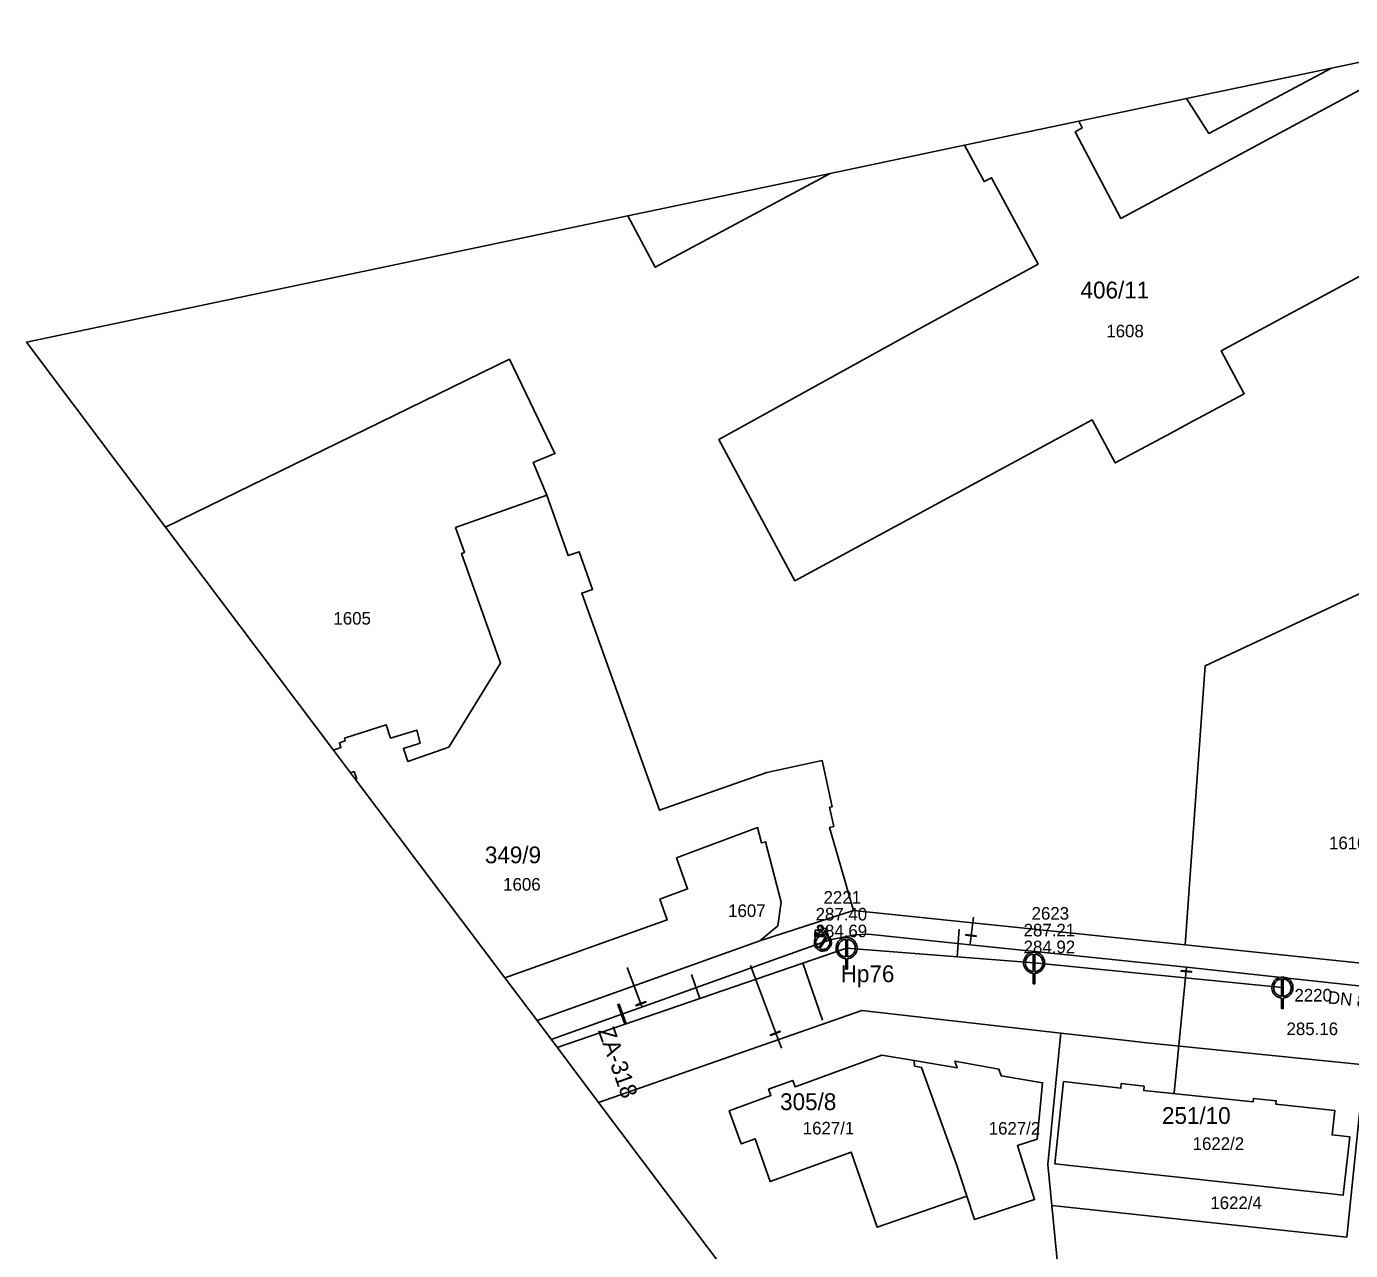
# Model space of a CAD drawing. Extents: x -570698 to -570232, y -1086952 to -1086596.
# Drawn here: x -570698.4 to -570540.7, y -1086773.3 to -1086627.6 of the extents above; entities that cross this region are included whole.
import ezdxf

# ---------------------------------------------------------------- set-up
doc = ezdxf.new("R2010")
doc.units = 0
for name, color, linetype in [('Adresní místo-text', 7, 'Continuous'), ('Armatura - popis', 7, 'Continuous'), ('Armatura vodovodní', 7, 'Continuous'), ('Default', 7, 'Continuous'), ('Hydrant', 7, 'Continuous'), ('Kanalizační přípojka', 7, 'Continuous'), ('Kanalizační stoka', 7, 'Continuous'), ('Kanalizační šachta', 7, 'Continuous'), ('Označení hydrantu', 7, 'Continuous'), ('Parcela-polygon', 7, 'Continuous'), ('Parcela-text', 7, 'Continuous'), ('Popis šachty', 7, 'Continuous'), ('Vodovodní přípojka', 7, 'Continuous'), ('Vodovodní řad', 7, 'Continuous'), ('Řad vodovodní popis', 7, 'Continuous')]:
    doc.layers.add(name, color=color, linetype=linetype)

msp = doc.modelspace()

# ---------------------------------------------------------------- linework, layer by layer
at = {"layer": 'Armatura vodovodní'}
for points in [[(-570586.5, -1086735.7), (-570585.26, -1086735.86), (-570585.27, -1086735.93), (-570586.51, -1086735.78), (-570586.5, -1086735.7)], [(-570560.83, -1086740), (-570559.59, -1086740.12), (-570559.6, -1086740.2), (-570560.84, -1086740.08), (-570560.83, -1086740)], [(-570627.8, -1086743.99), (-570626.96, -1086746.35), (-570627.11, -1086746.4), (-570627.95, -1086744.04), (-570627.8, -1086743.99)], [(-570625.79, -1086744.13), (-570624.62, -1086743.69), (-570624.6, -1086743.76), (-570625.76, -1086744.21), (-570625.79, -1086744.13)], [(-570608.56, -1086747.28), (-570609.73, -1086747.72), (-570609.76, -1086747.65), (-570608.59, -1086747.21), (-570608.56, -1086747.28)]]:
    msp.add_lwpolyline(points, dxfattribs=at)
at = {"layer": 'Default'}
for points, degree in [([(-570604.47, -1086735.76), (-570604.47, -1086735.48), (-570604.42, -1086735.2)], 2), ([(-570604.11, -1086735.33), (-570604.1, -1086735.01), (-570604.01, -1086734.73)], 2), ([(-570603.56, -1086735.5), (-570603.66, -1086735.2), (-570603.86, -1086734.96), (-570603.95, -1086735.25), (-570603.93, -1086735.57)], 3), ([(-570603.81, -1086734.69), (-570603.61, -1086734.91), (-570603.48, -1086735.21)], 2), ([(-570603.25, -1086734.96), (-570603.09, -1086735.21), (-570602.99, -1086735.46)], 2), ([(-570602.85, -1086735.92), (-570602.61, -1086736.14), (-570602.54, -1086736.48), (-570602.46, -1086736.88), (-570602.69, -1086737.23), (-570602.92, -1086737.57), (-570603.33, -1086737.65), (-570603.73, -1086737.73), (-570604.07, -1086737.5), (-570604.42, -1086737.27), (-570604.5, -1086736.87), (-570604.57, -1086736.53), (-570604.42, -1086736.23)], 3), ([(-570604.45, -1086736.27), (-570604.43, -1086736.25), (-570604.42, -1086736.23), (-570604.45, -1086736.07), (-570604.46, -1086735.96)], 3), ([(-570603.15, -1086735.94), (-570603.39, -1086735.81), (-570603.68, -1086735.87), (-570604.01, -1086735.94), (-570604.2, -1086736.22), (-570604.38, -1086736.5), (-570604.32, -1086736.83), (-570604.26, -1086737.11), (-570604.05, -1086737.29)], 3), ([(-570604.28, -1086735.43), (-570604.29, -1086735.71), (-570604.26, -1086735.99)], 2), ([(-570604.26, -1086735.99), (-570604.08, -1086735.79), (-570603.8, -1086735.71)], 2), ([(-570603.89, -1086737.39), (-570603.65, -1086737.52), (-570603.36, -1086737.46), (-570603.03, -1086737.4), (-570602.85, -1086737.12), (-570602.66, -1086736.84), (-570602.72, -1086736.51), (-570602.78, -1086736.23), (-570602.99, -1086736.05)], 3), ([(-570603.62, -1086735.67), (-570603.34, -1086735.64), (-570603.1, -1086735.76), (-570603.17, -1086735.49), (-570603.3, -1086735.23)], 3), ([(-570602.89, -1086735.77), (-570602.88, -1086735.8), (-570602.85, -1086735.92)], 2), ([(-570600.79, -1086738.58), (-570601.05, -1086738.56), (-570601.31, -1086738.41), (-570601.61, -1086738.25), (-570601.78, -1086737.95), (-570601.94, -1086737.65), (-570601.94, -1086737.33), (-570601.94, -1086737), (-570601.77, -1086736.7), (-570601.6, -1086736.4), (-570601.31, -1086736.24), (-570601.01, -1086736.08), (-570600.69, -1086736.08), (-570600.38, -1086736.08), (-570600.08, -1086736.24), (-570599.78, -1086736.4), (-570599.61, -1086736.7), (-570599.44, -1086737), (-570599.44, -1086737.33), (-570599.44, -1086737.65), (-570599.6, -1086737.95), (-570599.77, -1086738.25), (-570600.07, -1086738.41), (-570600.33, -1086738.56), (-570600.59, -1086738.58)], 3), ([(-570600.79, -1086736.29), (-570600.99, -1086736.31), (-570601.21, -1086736.42), (-570601.45, -1086736.56), (-570601.59, -1086736.81), (-570601.73, -1086737.06), (-570601.73, -1086737.33), (-570601.73, -1086737.6), (-570601.6, -1086737.85), (-570601.46, -1086738.09), (-570601.21, -1086738.23), (-570601, -1086738.35), (-570600.79, -1086738.37)], 3), ([(-570600.59, -1086738.37), (-570600.38, -1086738.35), (-570600.17, -1086738.23), (-570599.92, -1086738.09), (-570599.78, -1086737.85), (-570599.65, -1086737.6), (-570599.65, -1086737.33), (-570599.65, -1086737.06), (-570599.79, -1086736.81), (-570599.93, -1086736.56), (-570600.18, -1086736.42), (-570600.39, -1086736.31), (-570600.59, -1086736.29)], 3), ([(-570578.45, -1086740.33), (-570578.71, -1086740.31), (-570578.97, -1086740.16), (-570579.27, -1086740), (-570579.44, -1086739.7), (-570579.6, -1086739.4), (-570579.6, -1086739.08), (-570579.6, -1086738.75), (-570579.43, -1086738.45), (-570579.26, -1086738.15), (-570578.97, -1086737.99), (-570578.67, -1086737.83), (-570578.35, -1086737.83), (-570578.04, -1086737.83), (-570577.74, -1086737.99), (-570577.44, -1086738.15), (-570577.27, -1086738.45), (-570577.1, -1086738.75), (-570577.1, -1086739.08), (-570577.1, -1086739.4), (-570577.26, -1086739.7), (-570577.43, -1086740), (-570577.73, -1086740.16), (-570577.99, -1086740.31), (-570578.25, -1086740.33)], 3), ([(-570578.45, -1086738.04), (-570578.65, -1086738.06), (-570578.87, -1086738.17), (-570579.11, -1086738.31), (-570579.25, -1086738.56), (-570579.39, -1086738.81), (-570579.39, -1086739.08), (-570579.39, -1086739.35), (-570579.26, -1086739.6), (-570579.12, -1086739.84), (-570578.87, -1086739.98), (-570578.66, -1086740.1), (-570578.45, -1086740.12)], 3), ([(-570578.25, -1086740.12), (-570578.04, -1086740.1), (-570577.83, -1086739.98), (-570577.58, -1086739.84), (-570577.44, -1086739.6), (-570577.31, -1086739.35), (-570577.31, -1086739.08), (-570577.31, -1086738.81), (-570577.45, -1086738.56), (-570577.59, -1086738.31), (-570577.84, -1086738.17), (-570578.05, -1086738.06), (-570578.25, -1086738.04)], 3), ([(-570548.87, -1086743.29), (-570549.13, -1086743.27), (-570549.39, -1086743.12), (-570549.69, -1086742.96), (-570549.86, -1086742.66), (-570550.02, -1086742.36), (-570550.02, -1086742.04), (-570550.02, -1086741.71), (-570549.85, -1086741.41), (-570549.68, -1086741.11), (-570549.39, -1086740.95), (-570549.09, -1086740.79), (-570548.77, -1086740.79), (-570548.46, -1086740.79), (-570548.16, -1086740.95), (-570547.86, -1086741.11), (-570547.69, -1086741.41), (-570547.52, -1086741.71), (-570547.52, -1086742.04), (-570547.52, -1086742.36), (-570547.68, -1086742.66), (-570547.85, -1086742.96), (-570548.15, -1086743.12), (-570548.41, -1086743.27), (-570548.67, -1086743.29)], 3), ([(-570548.87, -1086741), (-570549.07, -1086741.02), (-570549.29, -1086741.13), (-570549.53, -1086741.27), (-570549.67, -1086741.52), (-570549.81, -1086741.77), (-570549.81, -1086742.04), (-570549.81, -1086742.31), (-570549.68, -1086742.56), (-570549.54, -1086742.8), (-570549.29, -1086742.94), (-570549.08, -1086743.06), (-570548.87, -1086743.08)], 3), ([(-570548.67, -1086743.08), (-570548.46, -1086743.06), (-570548.25, -1086742.94), (-570548, -1086742.8), (-570547.86, -1086742.56), (-570547.73, -1086742.31), (-570547.73, -1086742.04), (-570547.73, -1086741.77), (-570547.87, -1086741.52), (-570548.01, -1086741.27), (-570548.26, -1086741.13), (-570548.47, -1086741.02), (-570548.67, -1086741)], 3)]:
    msp.add_open_spline(points, degree=degree, dxfattribs=at)
at = {"layer": 'Hydrant'}
for points in [[(-570604.42, -1086735.2), (-570604.23, -1086735.16), (-570604.11, -1086735.33)], [(-570604.01, -1086734.73), (-570603.81, -1086734.69)], [(-570603.48, -1086735.21), (-570603.44, -1086735), (-570603.25, -1086734.96)], [(-570604.46, -1086735.96), (-570604.47, -1086735.76)], [(-570604.42, -1086736.23), (-570604.45, -1086736.27)], [(-570603.93, -1086735.57), (-570604.12, -1086735.61), (-570604.28, -1086735.43)], [(-570604.05, -1086737.29), (-570603.15, -1086735.94)], [(-570602.99, -1086736.05), (-570603.89, -1086737.39)], [(-570603.8, -1086735.71), (-570603.62, -1086735.67)], [(-570603.3, -1086735.23), (-570603.37, -1086735.46), (-570603.56, -1086735.5)], [(-570602.99, -1086735.46), (-570602.92, -1086735.66), (-570602.89, -1086735.77)]]:
    msp.add_lwpolyline(points, dxfattribs=at)
at = {"layer": 'Kanalizační přípojka'}
for points in [[(-570587.26, -1086735.07), (-570587.52, -1086738.36)], [(-570603.56, -1086745.93), (-570605.89, -1086739.11)], [(-570619.16, -1086740.49), (-570618.19, -1086743.33)]]:
    msp.add_lwpolyline(points, dxfattribs=at)
at = {"layer": 'Kanalizační stoka'}
for points in [[(-570600.69, -1086737.33), (-570619.34, -1086743.73), (-570635.16, -1086749.15)], [(-570578.35, -1086739.08), (-570600.69, -1086737.33)], [(-570548.77, -1086742.04), (-570578.35, -1086739.08)]]:
    msp.add_lwpolyline(points, dxfattribs=at)
at = {"layer": 'Kanalizační šachta'}
for points in [[(-570600.79, -1086738.37), (-570600.79, -1086736.29)], [(-570600.59, -1086736.29), (-570600.59, -1086738.37)], [(-570578.45, -1086740.12), (-570578.45, -1086738.04)], [(-570578.25, -1086738.04), (-570578.25, -1086740.12)], [(-570600.59, -1086738.58), (-570600.59, -1086739.83), (-570600.79, -1086739.83), (-570600.79, -1086738.58)], [(-570578.25, -1086740.33), (-570578.25, -1086741.58), (-570578.45, -1086741.58), (-570578.45, -1086740.33)], [(-570548.87, -1086743.08), (-570548.87, -1086741)], [(-570548.67, -1086741), (-570548.67, -1086743.08)], [(-570548.67, -1086743.29), (-570548.67, -1086744.54), (-570548.87, -1086744.54), (-570548.87, -1086743.29)]]:
    msp.add_lwpolyline(points, dxfattribs=at)
at = {"layer": 'Parcela-polygon'}
for p, q in [((-570519.33, -1086627.59), (-570542.91, -1086632.54)), ((-570542.91, -1086632.54), (-570560.18, -1086636.17)), ((-570560.18, -1086636.17), (-570573.04, -1086638.87)), ((-570573.04, -1086638.87), (-570586.66, -1086641.72)), ((-570586.66, -1086641.72), (-570602.65, -1086645.08)), ((-570602.65, -1086645.08), (-570626.76, -1086650.14)), ((-570681.81, -1086687.2), (-570661.8, -1086713.76)), ((-570661.8, -1086713.76), (-570659.78, -1086716.45)), ((-570659.78, -1086716.45), (-570659.18, -1086717.25)), ((-570659.18, -1086717.25), (-570641.39, -1086740.87)), ((-570641.39, -1086740.87), (-570637.57, -1086745.95)), ((-570637.57, -1086745.95), (-570630.23, -1086755.7)), ((-570630.23, -1086755.7), (-570596.4, -1086800.62))]:
    msp.add_line(p, q, dxfattribs=at)
for points in [[(-570573.04, -1086638.87), (-570572.61, -1086639.66), (-570573.47, -1086640.14), (-570568.01, -1086650.45), (-570529.62, -1086629.83), (-570526.63, -1086635.55), (-570520.52, -1086647.06), (-570556.06, -1086666.21), (-570553.32, -1086671.33), (-570559.43, -1086674.6), (-570562.57, -1086676.29), (-570568.69, -1086679.56), (-570571.43, -1086674.44), (-570606.85, -1086693.58), (-570613.01, -1086682.15), (-570615.91, -1086676.78), (-570591.52, -1086663.31), (-570577.88, -1086655.91), (-570579.95, -1086652.07), (-570583.42, -1086645.6), (-570584.32, -1086646.06), (-570586.66, -1086641.72)], [(-570586.66, -1086641.72), (-570584.32, -1086646.06), (-570583.42, -1086645.6), (-570579.95, -1086652.07), (-570577.88, -1086655.91), (-570591.52, -1086663.31), (-570615.91, -1086676.78), (-570613.01, -1086682.15), (-570606.85, -1086693.58), (-570571.43, -1086674.44), (-570568.69, -1086679.56), (-570562.57, -1086676.29), (-570559.43, -1086674.6), (-570553.32, -1086671.33), (-570556.06, -1086666.21), (-570520.52, -1086647.06), (-570526.63, -1086635.55), (-570529.62, -1086629.83), (-570568.01, -1086650.45), (-570573.47, -1086640.14), (-570572.61, -1086639.66), (-570573.04, -1086638.87)], [(-570542.91, -1086632.54), (-570557.52, -1086640.32), (-570560.18, -1086636.17)], [(-570560.18, -1086636.17), (-570557.52, -1086640.32), (-570542.91, -1086632.54)], [(-570602.65, -1086645.08), (-570623.48, -1086656.26), (-570626.76, -1086650.14)], [(-570626.76, -1086650.14), (-570623.48, -1086656.26), (-570602.65, -1086645.08)], [(-570626.76, -1086650.14), (-570698.39, -1086665.18), (-570681.81, -1086687.2)], [(-570681.81, -1086687.2), (-570640.86, -1086667.22), (-570635.43, -1086678.45), (-570638.02, -1086679.52), (-570636.41, -1086683.4), (-570633.84, -1086690.6), (-570632.55, -1086690.14), (-570630.95, -1086694.62), (-570632.23, -1086695.08), (-570622.99, -1086720.91), (-570622.41, -1086720.71), (-570610.18, -1086716.42), (-570603.59, -1086715), (-570602.42, -1086720.49), (-570602.72, -1086720.55), (-570602.22, -1086722.85), (-570602.71, -1086722.96), (-570599.85, -1086732.87), (-570560.36, -1086736.95), (-570560.32, -1086736.37), (-570557.96, -1086703.7), (-570525.43, -1086688.51)], [(-570661.8, -1086713.76), (-570660.92, -1086713.45), (-570661.1, -1086712.87), (-570660.41, -1086712.65), (-570660.51, -1086712.35), (-570655.52, -1086710.76), (-570655.01, -1086712.33), (-570651.88, -1086711.39), (-570651.49, -1086712.91), (-570653.48, -1086713.58), (-570652.96, -1086715.1), (-570648.09, -1086713.42), (-570641.91, -1086703.4), (-570646.56, -1086690.33), (-570646.21, -1086690.21), (-570647.26, -1086687.26), (-570636.41, -1086683.4), (-570638.02, -1086679.52), (-570635.43, -1086678.45), (-570640.86, -1086667.22), (-570681.81, -1086687.2)], [(-570641.39, -1086740.87), (-570622.05, -1086733.97), (-570622.93, -1086731.49), (-570619.63, -1086730.29), (-570620.95, -1086726.6), (-570611.31, -1086722.96), (-570610.84, -1086724.8), (-570610.35, -1086724.67), (-570608.49, -1086731.88), (-570608.9, -1086734.67), (-570611.04, -1086736.46), (-570599.85, -1086732.87), (-570602.71, -1086722.96), (-570602.22, -1086722.85), (-570602.72, -1086720.55), (-570602.42, -1086720.49), (-570603.59, -1086715), (-570610.18, -1086716.42), (-570622.41, -1086720.71), (-570622.99, -1086720.91), (-570632.23, -1086695.08), (-570630.95, -1086694.62), (-570632.55, -1086690.14), (-570633.84, -1086690.6), (-570636.41, -1086683.4), (-570647.26, -1086687.26), (-570646.21, -1086690.21), (-570646.56, -1086690.33), (-570641.91, -1086703.4), (-570648.09, -1086713.42), (-570652.96, -1086715.1), (-570653.48, -1086713.58), (-570651.49, -1086712.91), (-570651.88, -1086711.39), (-570655.01, -1086712.33), (-570655.52, -1086710.76), (-570660.51, -1086712.35), (-570660.41, -1086712.65), (-570661.1, -1086712.87), (-570660.92, -1086713.45), (-570661.8, -1086713.76)], [(-570659.18, -1086717.25), (-570659.04, -1086717.2), (-570659.35, -1086716.31), (-570659.78, -1086716.45)], [(-570659.78, -1086716.45), (-570659.35, -1086716.31), (-570659.04, -1086717.2), (-570659.18, -1086717.25)], [(-570637.57, -1086745.95), (-570611.04, -1086736.46), (-570608.9, -1086734.67), (-570608.49, -1086731.88), (-570610.35, -1086724.67), (-570610.84, -1086724.8), (-570611.31, -1086722.96), (-570620.95, -1086726.6), (-570619.63, -1086730.29), (-570622.93, -1086731.49), (-570622.05, -1086733.97), (-570641.39, -1086740.87)], [(-570510.36, -1086742.15), (-570560.36, -1086736.95), (-570599.85, -1086732.87), (-570611.04, -1086736.46), (-570637.57, -1086745.95)], [(-570596.4, -1086800.62), (-570574.22, -1086788.74), (-570574.42, -1086786.67), (-570574.78, -1086782.97), (-570576.24, -1086767.98), (-570576.71, -1086763.1), (-570575.63, -1086752.18), (-570575.16, -1086747.45), (-570598.86, -1086744.76), (-570630.23, -1086755.7)], [(-570630.23, -1086755.7), (-570598.86, -1086744.76), (-570575.16, -1086747.45), (-570566.93, -1086748.39), (-570565.31, -1086748.59), (-570538.98, -1086751.22)], [(-570578.29, -1086767.27), (-570585.46, -1086769.65), (-570586.37, -1086766.87), (-570597.03, -1086770.58), (-570600.13, -1086761.63), (-570609.78, -1086765.13), (-570611.6, -1086760.03), (-570613.26, -1086760.63), (-570614.67, -1086756.72), (-570609.71, -1086754.9), (-570609.99, -1086754.14), (-570607.11, -1086753.09), (-570606.83, -1086753.84), (-570596.51, -1086750.06), (-570592.64, -1086750.72), (-570587.53, -1086751.57), (-570587.79, -1086750.78), (-570582.56, -1086751.73), (-570582.28, -1086752.54), (-570577.34, -1086753.37), (-570578, -1086760.08), (-570580.35, -1086760.85), (-570578.29, -1086767.27)]]:
    msp.add_lwpolyline(points, dxfattribs=at)
for points in [[(-570522.15, -1086694.08), (-570522.76, -1086692.12), (-570525.43, -1086688.51), (-570557.96, -1086703.7), (-570560.32, -1086736.37), (-570560.36, -1086736.95), (-570510.36, -1086742.15), (-570510.36, -1086741.94), (-570510.48, -1086733.74), (-570510.81, -1086710.35), (-570513.51, -1086707.69), (-570519.18, -1086700.57), (-570520.57, -1086699.73), (-570523.79, -1086695.31)], [(-570575.16, -1086747.45), (-570575.63, -1086752.18), (-570576.71, -1086763.1), (-570576.24, -1086767.98), (-570541.1, -1086771.74), (-570538.98, -1086751.22), (-570565.31, -1086748.59), (-570566.93, -1086748.39)], [(-570586.37, -1086766.87), (-570587.57, -1086763.21), (-570591.76, -1086751.55), (-570592.6, -1086751.37), (-570592.64, -1086750.72), (-570596.51, -1086750.06), (-570606.83, -1086753.84), (-570607.11, -1086753.09), (-570609.99, -1086754.14), (-570609.71, -1086754.9), (-570614.67, -1086756.72), (-570613.26, -1086760.63), (-570611.6, -1086760.03), (-570609.78, -1086765.13), (-570600.13, -1086761.63), (-570597.03, -1086770.58)], [(-570587.57, -1086763.21), (-570586.37, -1086766.87), (-570585.46, -1086769.65), (-570578.29, -1086767.27), (-570580.35, -1086760.85), (-570578, -1086760.08), (-570577.34, -1086753.37), (-570582.28, -1086752.54), (-570582.56, -1086751.73), (-570587.79, -1086750.78), (-570587.53, -1086751.57), (-570592.64, -1086750.72), (-570592.6, -1086751.37), (-570591.76, -1086751.55)], [(-570538.98, -1086751.22), (-570541.1, -1086771.74), (-570576.24, -1086767.98), (-570574.78, -1086782.97), (-570568.21, -1086782.35), (-570534.55, -1086779.16), (-570535.32, -1086751.53)], [(-570574.85, -1086753.22), (-570575.87, -1086763.02), (-570543.63, -1086766.53), (-570541.52, -1086766.76), (-570540.75, -1086759.8), (-570542.86, -1086759.57), (-570542.54, -1086756.66), (-570549.55, -1086755.93), (-570549.51, -1086755.51), (-570552.23, -1086755.23), (-570552.27, -1086755.65), (-570565.3, -1086754.29), (-570565.25, -1086753.79), (-570567.97, -1086753.46), (-570568.02, -1086754.01)], [(-570565.25, -1086753.79), (-570565.3, -1086754.29), (-570552.27, -1086755.65), (-570552.23, -1086755.23), (-570549.51, -1086755.51), (-570549.55, -1086755.93), (-570542.54, -1086756.66), (-570542.86, -1086759.57), (-570540.75, -1086759.8), (-570541.52, -1086766.76), (-570543.63, -1086766.53), (-570575.87, -1086763.02), (-570574.85, -1086753.22), (-570568.02, -1086754.01), (-570567.97, -1086753.46)]]:
    msp.add_lwpolyline(points, close=True, dxfattribs=at)
at = {"layer": 'Vodovodní přípojka'}
msp.add_line((-570561.65, -1086754.58), (-570560.21, -1086739.6), dxfattribs=at)
for points in [[(-570585.98, -1086736.81), (-570585.58, -1086733.63)], [(-570625.05, -1086744.34), (-570625.19, -1086743.95), (-570626.83, -1086739.64)], [(-570612.15, -1086739.4), (-570608.46, -1086749.26)]]:
    msp.add_lwpolyline(points, dxfattribs=at)
at = {"layer": 'Vodovodní řad'}
msp.add_lwpolyline([(-570635.87, -1086748.2), (-570627.45, -1086745.2), (-570625.99, -1086744.67), (-570622.64, -1086743.48), (-570608.59, -1086738.45), (-570602.7, -1086736.35), (-570599.65, -1086735.74), (-570598.11, -1086735.69), (-570585.97, -1086736.95), (-570560.21, -1086739.6), (-570525.45, -1086743.38), (-570521.77, -1086743.64), (-570506.17, -1086745.67), (-570467.77, -1086749.15), (-570443.58, -1086752.53)], dxfattribs=at)

# ---------------------------------------------------------------- texts
at = {"layer": 'Adresní místo-text'}
for s, p in [('406/11', (-570572.82, -1086659.97)), ('349/9', (-570643.78, -1086727.23)), ('305/8', (-570608.61, -1086756.62)), ('251/10', (-570563.12, -1086758.27))]:
    msp.add_text(s, height=2, dxfattribs=at).set_placement(p)
at = {"layer": 'Armatura - popis'}
msp.add_text('ZA-318', height=2, rotation=289.6687, dxfattribs=at).set_placement((-570630.34, -1086747.14))
at = {"layer": 'Označení hydrantu'}
msp.add_text('Hp76', height=2, dxfattribs=at).set_placement((-570601.39, -1086741.39))
at = {"layer": 'Parcela-text'}
for s, p in [('1608', (-570569.75, -1086664.6)), ('1605', (-570661.82, -1086698.81)), ('1610/1', (-570543.22, -1086725.56)), ('1606', (-570641.6, -1086730.49)), ('1607', (-570614.8, -1086733.63)), ('1627/1', (-570605.91, -1086759.52)), ('1627/2', (-570583.76, -1086759.54)), ('1622/2', (-570559.47, -1086761.36)), ('1622/4', (-570557.36, -1086768.41))]:
    msp.add_text(s, height=1.5, dxfattribs=at).set_placement(p)
at = {"layer": 'Popis šachty'}
for s, p in [('2221', (-570603.43, -1086732.04)), ('287.40', (-570604.38, -1086734.04)), ('2623', (-570578.65, -1086733.94)), ('284.69', (-570604.38, -1086736.04)), ('287.21', (-570579.6, -1086735.94)), ('284.92', (-570579.6, -1086737.94)), ('2220', (-570547.34, -1086743.69)), ('285.16', (-570548.28, -1086747.69))]:
    msp.add_text(s, height=1.5, dxfattribs=at).set_placement(p)
at = {"layer": 'Řad vodovodní popis'}
msp.add_text('DN 80 LTH', height=1.5, rotation=353.7827, dxfattribs=at).set_placement((-570543.41, -1086743.91))

doc.saveas('drawing.dxf')
